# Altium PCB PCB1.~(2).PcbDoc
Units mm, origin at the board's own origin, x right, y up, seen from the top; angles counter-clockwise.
Board outline 152.4 x 101.6 mm, 2 copper layers (Top Layer, Bottom Layer); 6 components, 6 nets, 51 pads, 0 vias.
Unrouted connection lines stored in the file: 13.
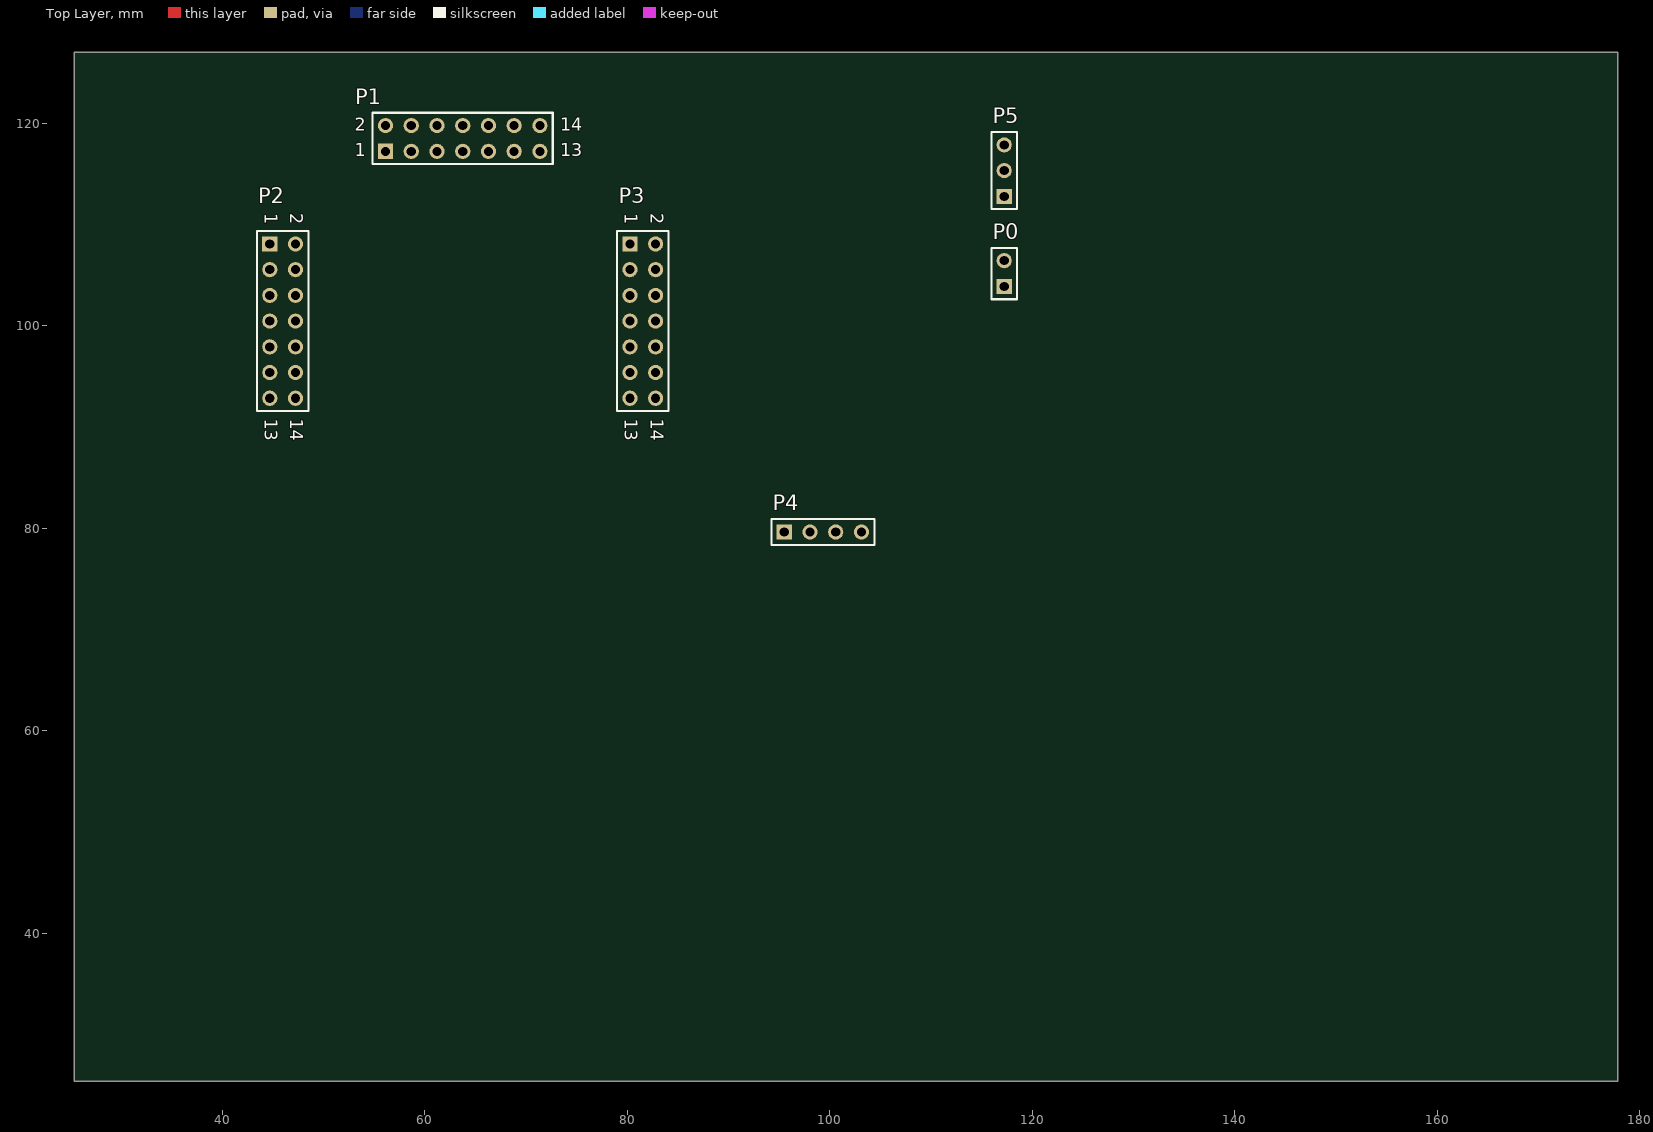
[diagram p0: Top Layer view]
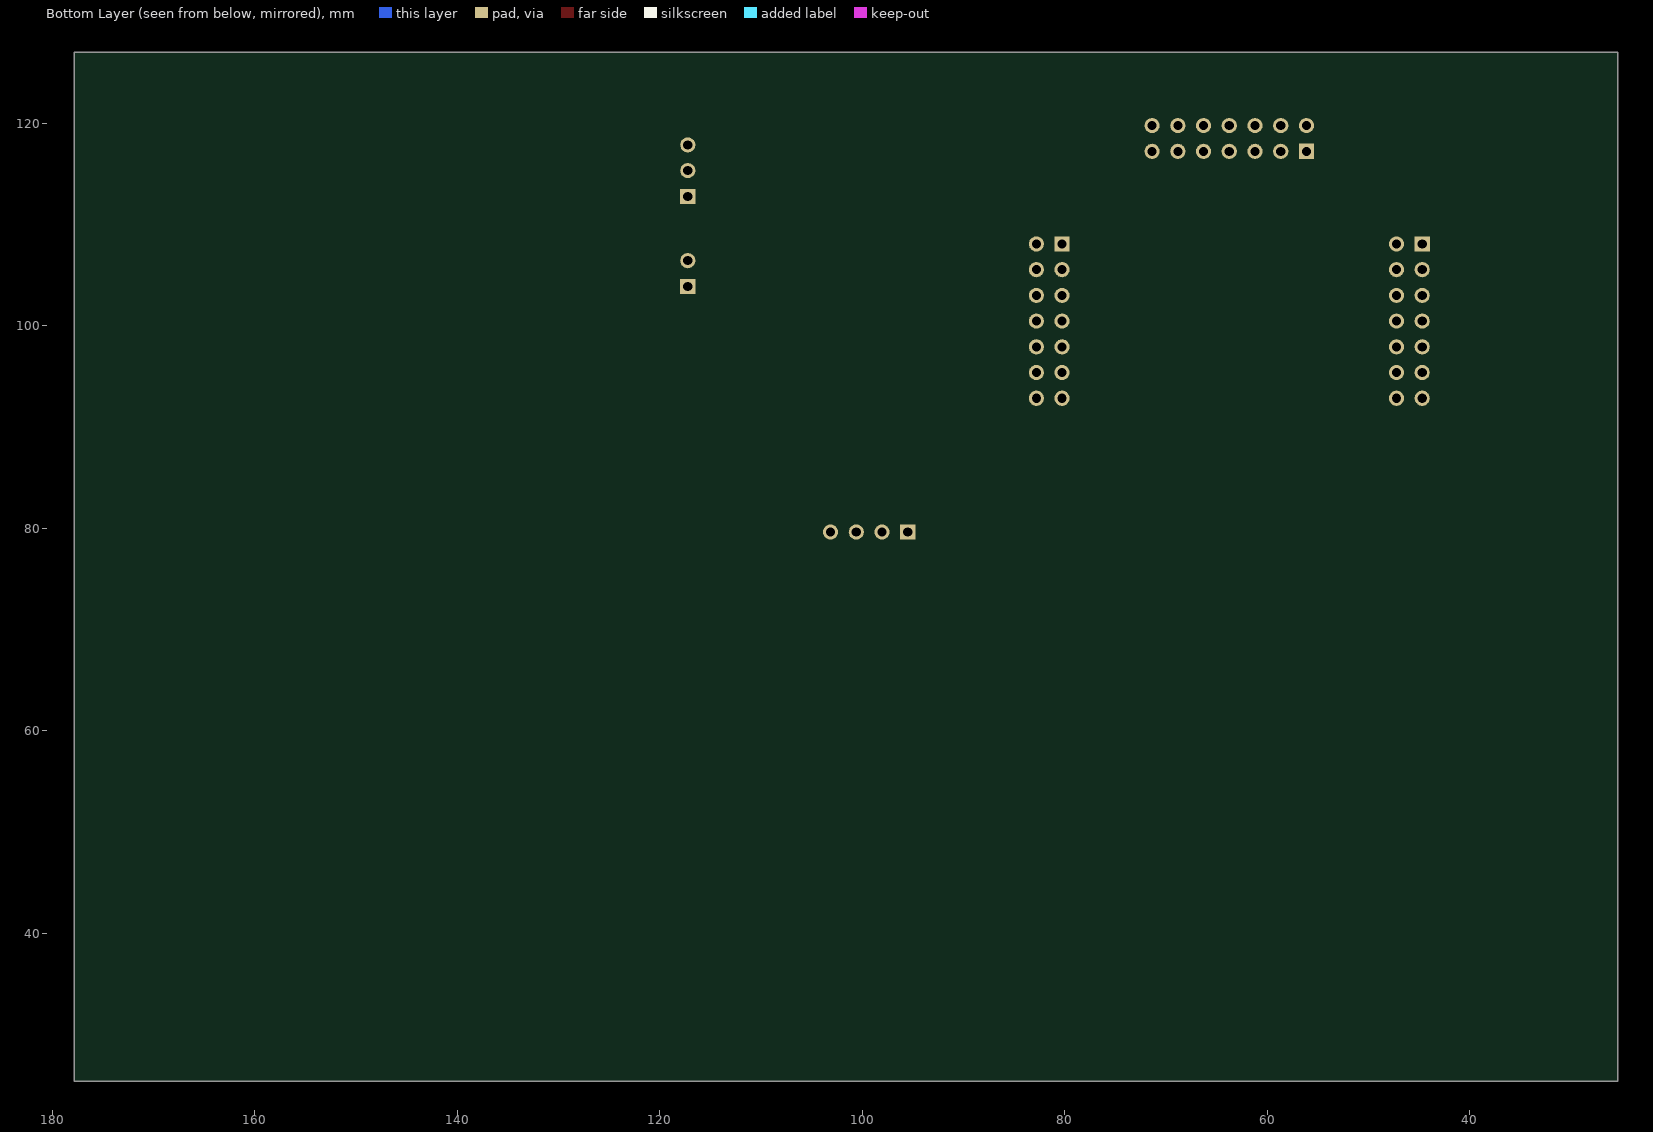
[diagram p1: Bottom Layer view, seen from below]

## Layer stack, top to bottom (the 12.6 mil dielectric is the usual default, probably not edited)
Top Solder: solder mask 0.0102, Solder Resist, Dk 3.5
Top Layer: signal copper 0.0356
Dielectric 1: dielectric 0.32, FR-4, Dk 4.8
Bottom Layer: signal copper 0.0356
Bottom Solder: solder mask 0.0102, Solder Resist, Dk 3.5

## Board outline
25.4,25.4 177.8,25.4 177.8,127 25.4,127

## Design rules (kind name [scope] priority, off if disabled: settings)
Clearance [All] p1: gap=0.254 ignorepadtopadclearanceinfootprint=FALSE
PolygonConnect [All] p1: connectstyle=Relief reliefconductorwidth=0.254 reliefentries=4 polygonreliefangle="90 Angle" airgapwidth=0.254
RoutingVias [All] p1: holewidth=0.711 width=1.27 viastyle="Through Hole" minholewidth=0.711 minwidth=1.27 maxholewidth=0.711 maxwidth=1.27
SolderMaskExpansion [All] p1: expansion=0.102 istentingtop=FALSE
SupplyNets "Schematic Supply Nets_2" [InNet('VCC')] p1: voltage=0.000
SupplyNets "Schematic Supply Nets_1" [InNet('GND')] p2: voltage=0.000
SupplyNets "Schematic Supply Nets" [InNet('3.3v')] p3: voltage=0.000
Width [All] p1: maxlimit=0.254 minlimit=0.254 preferedwidth=0.254
30 further rules are at their usual default settings.

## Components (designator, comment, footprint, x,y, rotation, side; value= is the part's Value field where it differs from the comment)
P0 "Header 2" HDR1X2 117.221,103.886 r90 top
P1 "Header 7X2" HDR2X7 56.134,117.221 r0 top
P2 "Header 7X2" HDR2X7 44.704,108.077 r270 top
P3 "Header 7X2" HDR2X7 80.264,108.077 r270 top
P4 "Header 4" HDR1X4 95.504,79.629 r0 top
P5 "Header 3" HDR1X3 117.221,112.776 r90 top

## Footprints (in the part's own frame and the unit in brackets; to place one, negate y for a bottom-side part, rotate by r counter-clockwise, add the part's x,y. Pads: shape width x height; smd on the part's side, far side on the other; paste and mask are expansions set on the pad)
HDR1X2 [mm] "Connector; Header; 2 Position"
  rect 1.5x1.5 hole 0.9: 1(0,0)
  round 1.5 hole 0.9: 2(2.54,0)
  silkscreen extent -1.27,-1.27 3.81,1.27, body extent -1.27,-1.28 3.81,1.26, height 8.79
HDR1X3 [mm] "Connector; Header; 3 Position"
  rect 1.5x1.5 hole 0.9: 1(0,0)
  round 1.5 hole 0.9: 2(2.54,0) 3(5.08,0)
  silkscreen extent -1.27,-1.27 6.35,1.27, body extent -1.26,-1.27 6.36,1.27, height 8.38
HDR1X4 [mm] "Connector; Header; 4 Position"
  rect 1.5x1.5 hole 0.9: 1(0,0)
  round 1.5 hole 0.9: 2(2.54,0) 3(5.08,0) 4(7.62,0)
  silkscreen extent -1.27,-1.27 8.89,1.27, body extent -1.27,-1.28 8.89,1.26, height 8.38
HDR2X7 [mm] "Connector; Header; 7x2 Position"
  rect 1.5x1.5 hole 0.9: 1(0,0)
  round 1.5 hole 0.9: 2(0,2.54) 3(2.54,0) 4(2.54,2.54) 5(5.08,0) 6(5.08,2.54) 7(7.62,0) 8(7.62,2.54) 9(10.16,0) 10(10.16,2.54) 11(12.7,0) 12(12.7,2.54) 13(15.24,0) 14(15.24,2.54)
  silkscreen extent -1.27,-1.27 16.51,3.81

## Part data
P0: "Header, 2-Pin"
P1 P2 P3: "Header, 7-Pin, Dual row"
P4: "Header, 4-Pin"
P5: "Header, 3-Pin"

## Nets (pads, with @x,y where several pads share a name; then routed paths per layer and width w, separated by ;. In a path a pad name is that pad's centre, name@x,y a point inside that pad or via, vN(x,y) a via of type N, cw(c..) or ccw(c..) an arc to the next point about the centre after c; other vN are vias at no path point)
3.3v: P1.14 P2.14 P5.2
GND: P0.2 P1.1 P1.13 P2.13 P3.14 P4.1 P5.3
rx: P3.11 P4.2
"signal finger": P2.10 P5.1
tx: P3.10 P4.3
VCC: P0.1 P1.2 P4.4
pads on no net: P1.3 P1.4 P1.5 P1.6 P1.7 P1.8 P1.9 P1.10 P1.11 P1.12 P2.1 P2.2 P2.3 P2.4 P2.5 P2.6 P2.7 P2.8 P2.9 P2.11 P2.12 P3.1 P3.2 P3.3 P3.4 P3.5 P3.6 P3.7 P3.8 P3.9 P3.12 P3.13

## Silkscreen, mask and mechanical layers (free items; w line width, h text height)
Mechanical 1:
  lines w0.254: 41.402,76.327 41.402,109.982 52.07,109.982 52.07,122.301 118.999,122.301 118.999,76.327 41.402,76.327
